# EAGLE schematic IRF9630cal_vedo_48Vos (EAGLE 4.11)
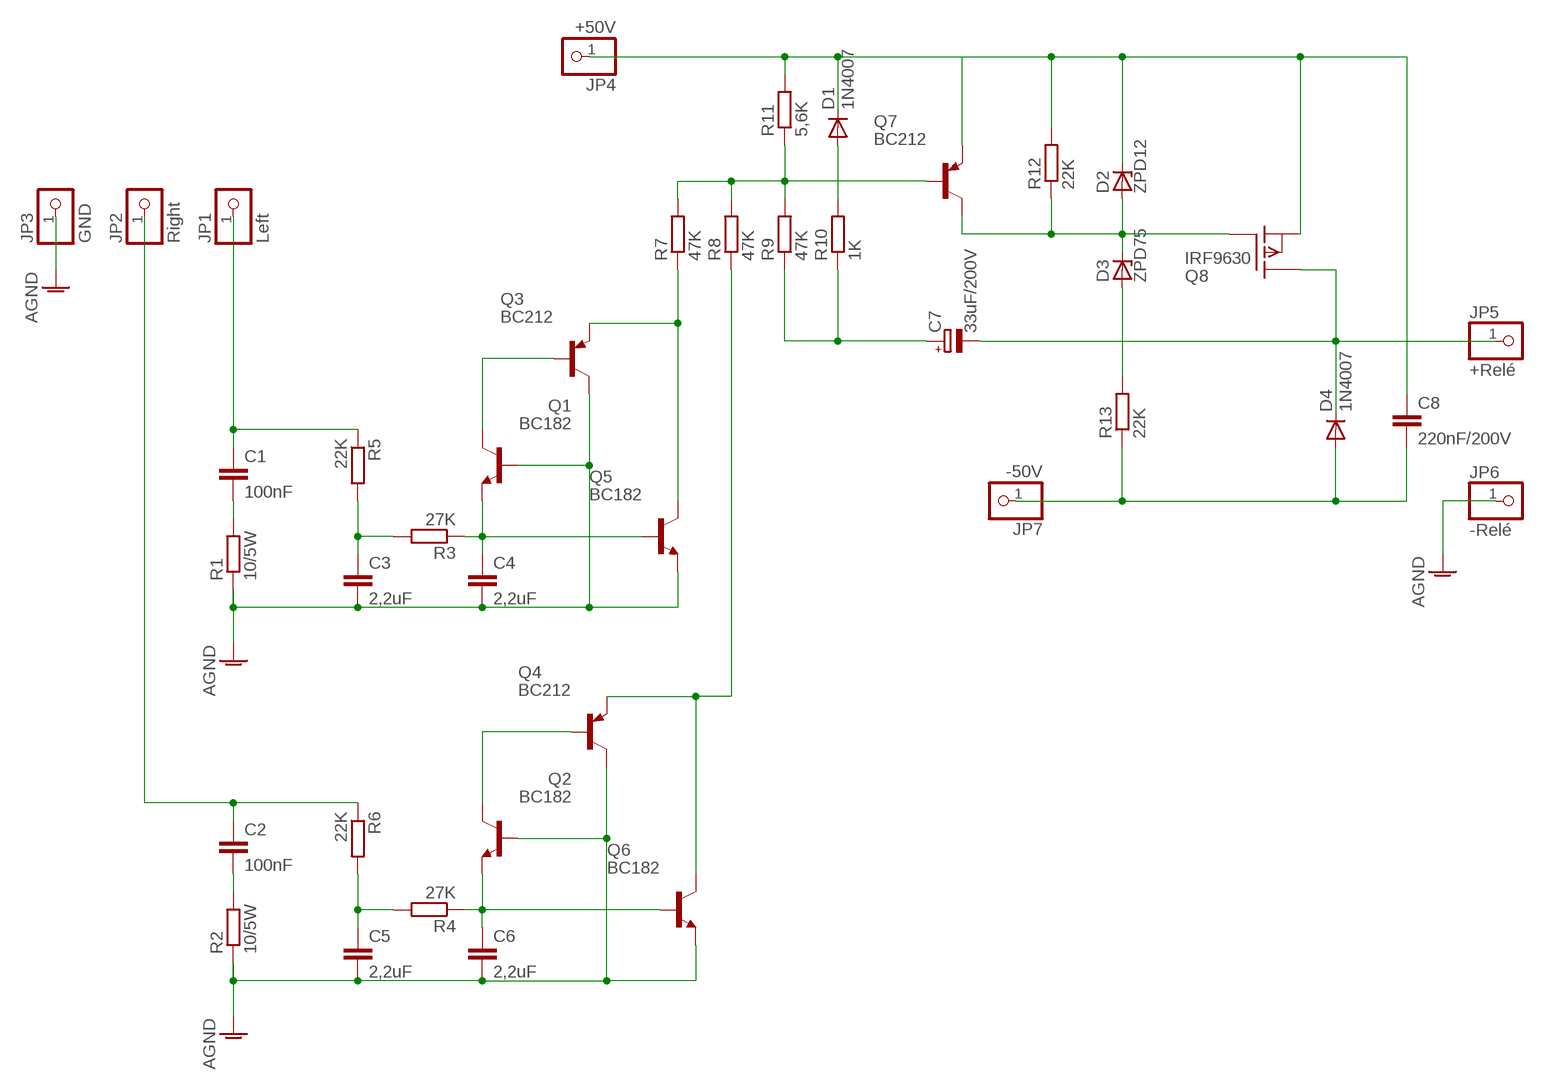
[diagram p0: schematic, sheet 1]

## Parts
C1  100nF  C-EU050-075X075  [C050-075X075]
C2  100nF  C-EU050-075X075  [C050-075X075]
C3  2,2uF  C-EU050-045X075  [C050-045X075]
C4  2,2uF  C-EU050-045X075  [C050-045X075]
C5  2,2uF  C-EU050-045X075  [C050-045X075]
C6  2,2uF  C-EU050-045X075  [C050-045X075]
C7  33uF/200V  CPOL-EUE5-8.5  [E5-8,5]
C8  220nF/200V  C-EU102_152-062X184  [C102_152-062X184]
D1  1N4007  1N4004  [DO41-10]
D2  ZPD12  ZPD  [DO35Z10]
D3  ZPD75  ZPD  [DO35Z10]
D4  1N4007  1N4004  [DO41-10]
JP1  Left  PINHD-1X1  [1X01]
JP2  Right  PINHD-1X1  [1X01]
JP3  GND  PINHD-1X1  [1X01]
JP4  +50V  PINHD-1X1  [1X01]
JP5  +Relé  PINHD-1X1  [1X01]
JP6  -Relé  PINHD-1X1  [1X01]
JP7  -50V  PINHD-1X1  [1X01]
Q1  BC182  BC237  [TO92]
Q2  BC182  BC237  [TO92]
Q3  BC212  BC214  [TO92]
Q4  BC212  BC214  [TO92]
Q5  BC182  BC237  [TO92]
Q6  BC182  BC237  [TO92]
Q7  BC212  BC214  [TO92]
Q8  IRF9630  IRF9530  [TO220]
R1  10/5W  R-EU_0922/22  [0922/22]
R2  10/5W  R-EU_0922/22  [0922/22]
R3  27K  R-EU_0207/12  [0207/12]
R4  27K  R-EU_0207/12  [0207/12]
R5  22K  R-EU_0207/12  [0207/12]
R6  22K  R-EU_0207/12  [0207/12]
R7  47K  R-EU_0207/12  [0207/12]
R8  47K  R-EU_0207/12  [0207/12]
R9  47K  R-EU_0207/12  [0207/12]
R10  1K  R-EU_0207/12  [0207/12]
R11  5,6K  R-EU_0207/12  [0207/12]
R12  22K  R-EU_0207/12  [0207/12]
R13  22K  R-EU_0207/12  [0207/12]

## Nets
N$1: C1.2 R1.2
N$2: C1.1 JP1.1 R5.1
N$3: C3.1 R3.2 R5.2
N$5: Q1.3(C) Q3.2(B)
N$6: D2.A D3.C Q7.3(C) Q8.1(G) R12.1
N$7: Q3.1(E) Q5.3(C) R7.1
N$8: Q4.1(E) Q6.3(C) R8.1
N$9: Q2.3(C) Q4.2(B)
N$10: C5.1 R4.2 R6.2
N$12: C4.1 Q1.1(E) Q5.2(B) R3.1
N$13: C2.2 R2.2
N$14: C2.1 JP2.1 R6.1
N$15: Q7.2(B) R7.2 R8.2 R9.2 R11.1
N$16: C8.1 D1.A D1.C D2.C JP4.1 Q7.1(E) Q8.3(S) R10.2 R11.2 R12.2
N$18: C7.+ R9.1 R10.1
N$19: C3.2 C4.2 C5.2 C6.2 JP3.1 JP6.1 Q1.2(B) Q2.2(B) Q3.3(C) Q4.3(C) Q5.1(E) Q6.1(E) R1.1 R2.1 ; supply symbol labelled AGND
N$20: D3.A R13.2
N$21: C8.2 D4.A JP7.1 R13.1
N$23: C6.1 Q2.1(E) Q6.2(B) R4.1
N$35: C7.- D4.C JP5.1 Q8.2(D)

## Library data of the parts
C1-C6 C8 = rcl:C-EU: CAPACITOR, European symbol
C7 = rcl:CPOL-EU: POLARIZED CAPACITOR, European symbol
D1 D4 = diode:1N4004: DIODE
D2 D3 = diode:ZPD: Z DIODE
JP1-JP7 = pinhead:PINHD-1X1: PIN HEADER
Q1 Q2 Q5 Q6 = transistor-npn:BC237: NPN Transistor
Q3 Q4 Q7 = transistor-pnp:BC214: PNP Transistor
Q8 = transistor-fet:IRF9530: P-Channel Enhancement MOSFET (HEXFET); -100V; -12A; 0,3Ohm
R1-R13 = rcl:R-EU_: RESISTOR, European symbol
